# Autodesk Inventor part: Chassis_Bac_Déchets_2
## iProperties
Created: 2009-01
Part Number: Chassis_Bac_Déchets_2
Document SubType Name: Modeling
Designer: claivier
Author: claivier
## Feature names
1. Extrusion1
2. Balayage1
3. Extrusion2
4. Dépouille de face2
5. Congé1 [Fillet]
6. Miroir1 [Mirror]
7. Congé2 [Fillet]
8. Coque1
9. Extrusion3
